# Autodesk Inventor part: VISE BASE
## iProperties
Created: 2006-07
Part Number: VISE BASE
Material: Cast Iron
Document SubType Name: Modeling
Designer: rollin42
Density: 7.25 g/cm^3
Author: rollin42
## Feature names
1. Extrusion1
2. Extrusion2
3. Extrusion3
4. Extrusion4
5. Fillet1
6. Fillet2
7. Fillet3
8. Extrusion5
9. Fillet4
10. Extrusion6
11. Mirror1
12. Hole1
13. Coil1
